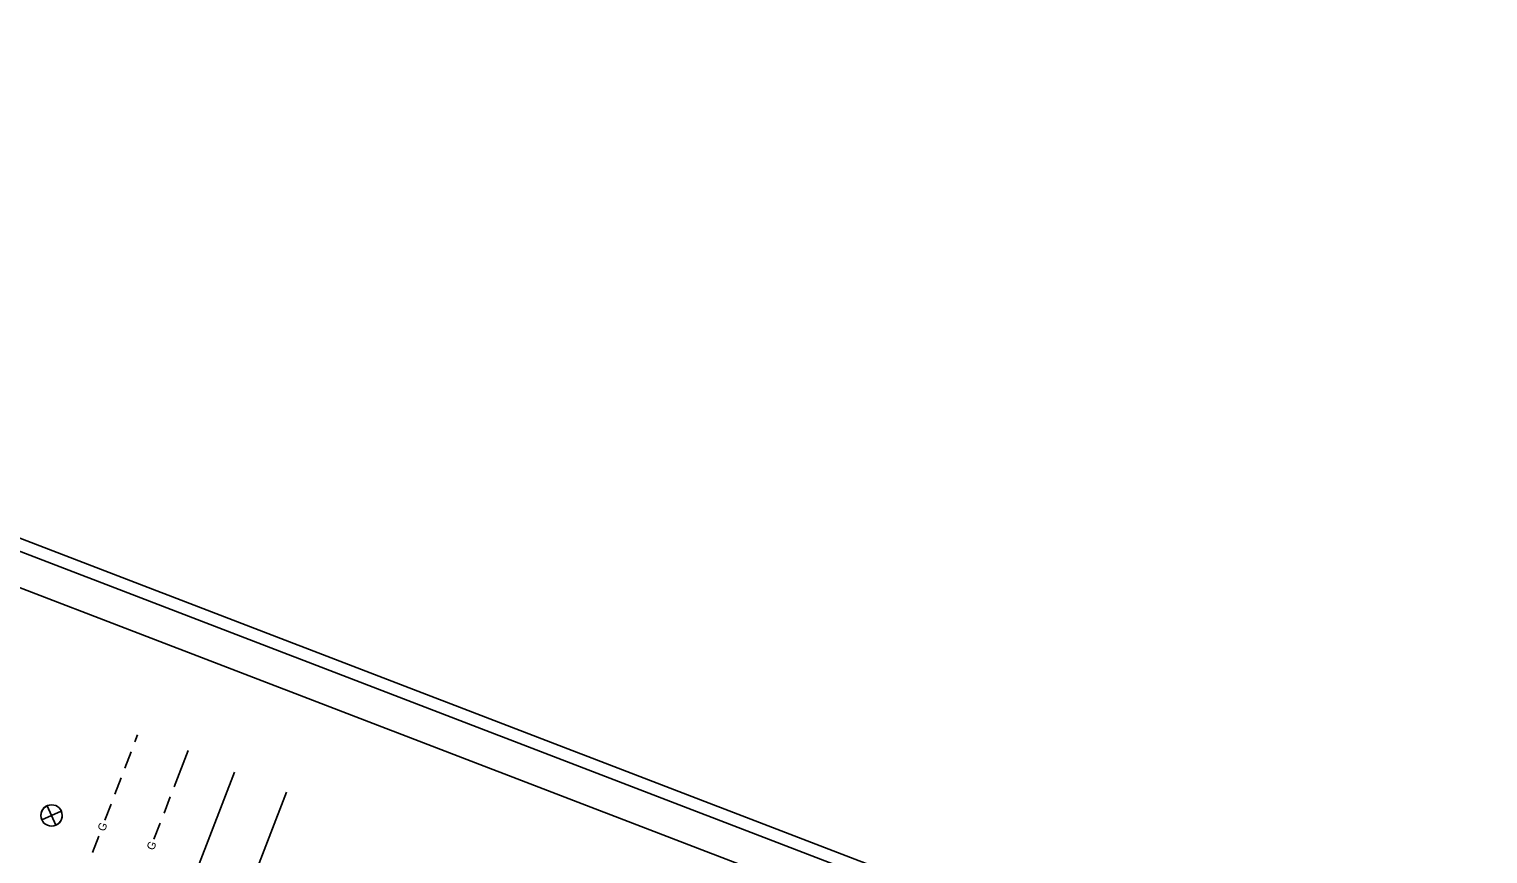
# Model space of a CAD drawing. Extents: x 1015221 to 1064345, y 619216 to 647967.
# Drawn here: x 1051569 to 1055860, y 634941 to 637366 of the extents above; entities that cross this region are included whole.
import ezdxf

# ---------------------------------------------------------------- set-up
doc = ezdxf.new("R2010")
doc.units = 0
for name, color, linetype in [('Default', 7, 'Continuous'), ('Sheet Plot Border Inside CELL', 7, 'Continuous'), ('Sheet Plot Border Outside CELL', 7, 'Continuous'), ('Sheet Symbology CELL', 7, 'Continuous')]:
    doc.layers.add(name, color=color, linetype=linetype)

msp = doc.modelspace()

# ---------------------------------------------------------------- linework, layer by layer
at = {"layer": 'Default'}
for p, q in [((1051880.2, 635269.9), (1051888.1, 635290.4)), ((1051850.7, 635193), (1051869, 635240.6)), ((1051995.1, 635137.5), (1052036.4, 635245)), ((1051821.1, 635116.1), (1051839.4, 635163.7)), ((1052069.1, 634911.4), (1052172.7, 635181.1)), ((1051965.6, 635060.6), (1051983.9, 635108.2)), ((1052100.4, 634536.4), (1052325.5, 635122.3)), ((1051791.6, 635039.2), (1051809.9, 635086.8)), ((1051936, 634983.7), (1051954.3, 635031.3)), ((1051755.3, 634944.7), (1051773.6, 634992.3))]:
    msp.add_line(p, q, dxfattribs=at)
for points in [[(1051622, 635082.2), (1051647.5, 635024.9), (1051634.7, 635053.5), (1051606.1, 635040.8), (1051663.4, 635066.3)], [(1051606.1, 635040.8), (1051634.7, 635053.5), (1051622, 635082.2)], [(1051663.4, 635066.3), (1051634.7, 635053.5), (1051647.5, 635024.9)]]:
    msp.add_lwpolyline(points, dxfattribs=at)
msp.add_circle((1051634.7, 635053.5), 31.4, dxfattribs=at)
for start, end in [(113.983, 203.983), (293.983, 23.983)]:
    msp.add_arc((1051634.7, 635053.5), 31.4, start, end, dxfattribs=at)
at = {"layer": 'Sheet Plot Border Inside CELL'}
msp.add_lwpolyline([(1050898.2, 621795.3), (1055679.6, 634240.3), (1047800.3, 637267.6), (1043018.9, 624822.5)], close=True, dxfattribs=at)
at = {"layer": 'Sheet Plot Border Outside CELL'}
msp.add_lwpolyline([(1051028.5, 621633.8), (1055860.2, 634209.5), (1047645.6, 637365.6), (1042813.9, 624789.8)], close=True, dxfattribs=at)
at = {"layer": 'Sheet Symbology CELL'}
msp.add_lwpolyline([(1047783.5, 637166.9), (1043479.8, 625965.2), (1051313.4, 622955.5), (1055617.1, 634157.2)], close=True, dxfattribs=at)

# ---------------------------------------------------------------- texts
at = {"layer": 'Default'}
for p in [(1051791, 635004.9), (1051935.5, 634949.4)]:
    msp.add_text('G', height=23.5, rotation=68.983, dxfattribs=at).set_placement(p)

doc.saveas('drawing.dxf')
